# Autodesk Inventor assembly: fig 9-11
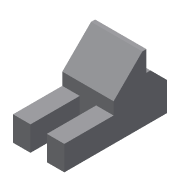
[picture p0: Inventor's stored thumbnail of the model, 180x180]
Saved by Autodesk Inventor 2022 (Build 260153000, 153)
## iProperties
Created: 2002-01
Part Number: fig 9-11
Document SubType Name: Assembly
Designer: ***
Control State: 0
Master: False
Checked Out: False
Shininess: 64.0
Length Units: 11269
Angle Units: 11279
Time Units: 11290
Mass Units: 11283
Length Display Precision: 3
Angle Display Precision: 2
Density: 0.0
Volumn: 0.0
Area: 0.0
PropertySet Name: Model Information
Author: ***
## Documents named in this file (3)
- D:\PROJECTS_2021\Resources\Part Files\c09_Inv_2022_prt\fig 9-11.iam
- D:\PROJECTS_2021\Resources\Part Files\c09_Inv_2022_prt\Part3.ipt
- D:\PROJECTS_2021\Resources\Part Files\c09_Inv_2022_prt\Part4.ipt
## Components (2 placed, 2 different names)
1. Part3:1 — Mate:1
2. Part4:1 — Mate:1
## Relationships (1: Mate 1)
- Mate:1: Part3:1 ↔ Part4:1
